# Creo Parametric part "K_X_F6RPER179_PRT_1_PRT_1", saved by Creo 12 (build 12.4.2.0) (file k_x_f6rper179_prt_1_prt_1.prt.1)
Units: Custom; MM, KILOGRAM, SECS

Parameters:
  PTC_WM_ITERATION = "0"
  PTC_WM_VERSION = "-.0"
  PTC_WM_LIFECYCLE_STATE = "In Work"
  PTC_WM_LIFECYCLE = "MO_CADDocument"
  PTC_WM_CREATED_BY = "Maximilian Roepper (Z0017RMS: MO)"
  PTC_WM_CREATED_ON = "18-Sep-26 11:36:42 AM"
  PTC_WM_MODIFIED_BY = "Maximilian Roepper (Z0017RMS: MO)"
  PTC_WM_MODIFIED_ON = "18-Sep-26 11:36:46 AM"
  PDMLINKNUMBER = "PDM000071454885"
  PTC_WM_NAME = "k_x_f6rper179_prt_1_prt_1.prt"
  PTC_WM_NUMBER = "PDM000071454885"

Other parameters: WEIGHT, WEIGHT_FACTOR, WEIGHT_ADD, _MASS_TEMP, _DIFF_TEMP, MC_ERRORS, SUPPLIER

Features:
  1. coordinate system
  2. datum plane "PRT_YZ"
  3. datum plane "PRT_XY"
  4. datum plane "PRT_XZ"
  5. coordinate system
  6. datum axis
  7. datum axis
  8. datum axis
  9. coordinate system
  10. imported feature
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
Other named items: PRT, SIEMENS_MO, DRW_VIEW_ORG, PRT_X, PRT_Y, PRT_Z, CS0, ROUGH_GROB

Layers: 00_STD_CSYS-KSYS, 01_STD_PLANES-EBENEN, 02_STD_AXES-ACHSEN, 03_STD_CSYS-KSYS, 24_IMPORT_FEAT-IMPORT_KE

Surfaces: 25 tabulated cylinder, 4 plane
